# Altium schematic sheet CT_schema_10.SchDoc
size 278 x 170 mm
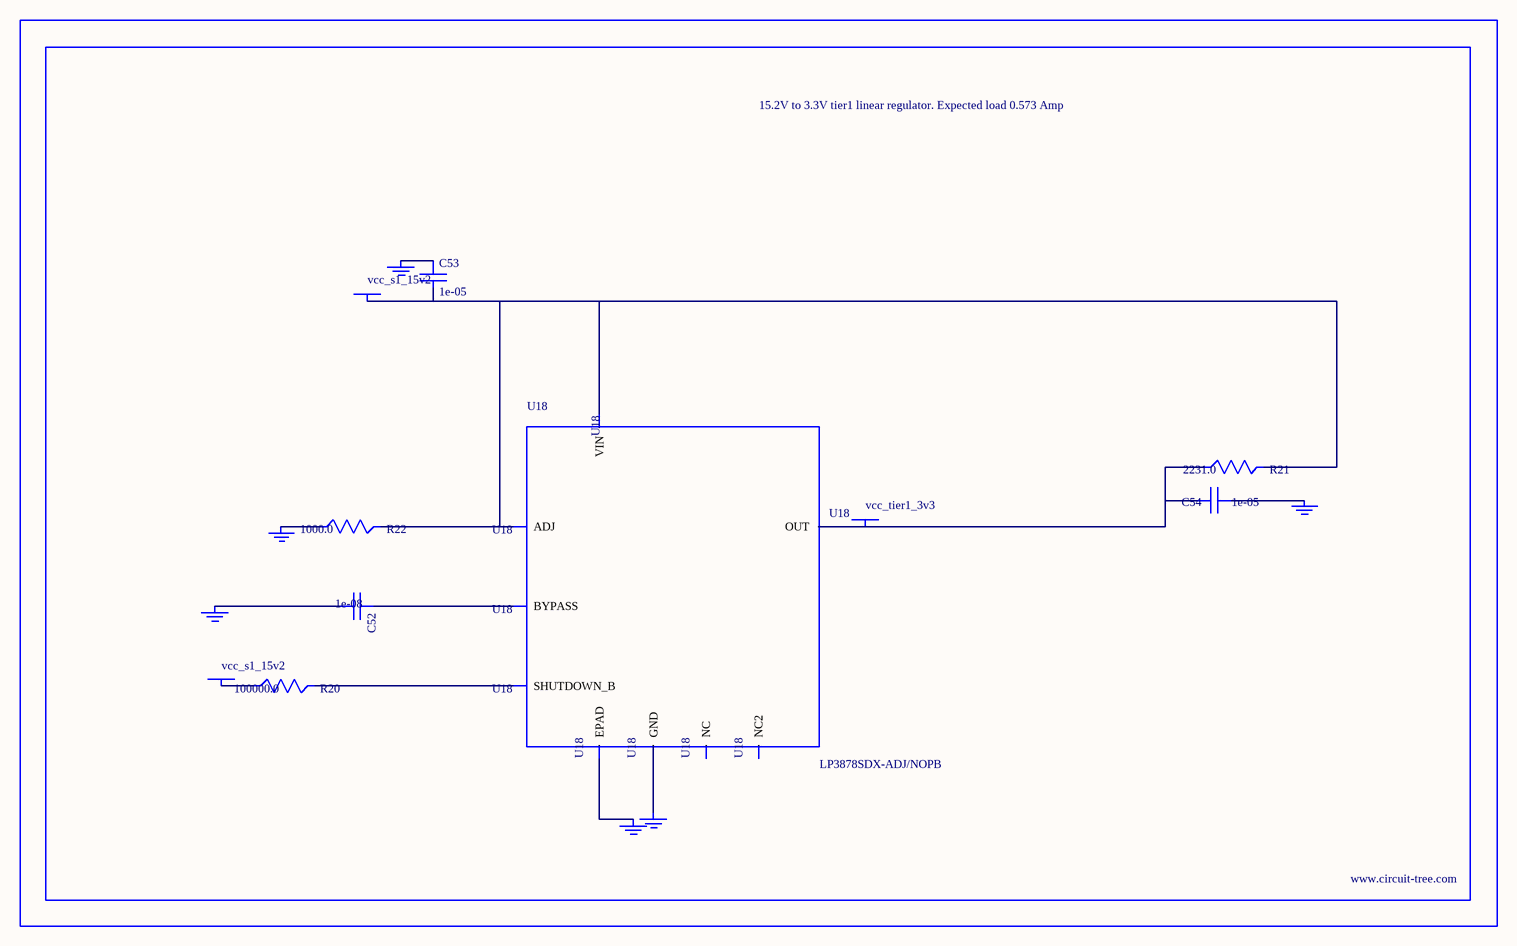
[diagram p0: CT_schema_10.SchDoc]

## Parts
BORDER9  (no value)
C52  1e-08  [C0402]
C53  1e-05  [C1210]
C54  1e-05  [C1210]
GND_INSTANCE_9_0  (no value)
GND_INSTANCE_9_1  (no value)
GND_INSTANCE_9_2  (no value)
GND_INSTANCE_9_3  (no value)
GND_INSTANCE_9_4  (no value)
GND_INSTANCE_9_5  (no value)
POWER_INSTANCE_9_0  vcc_s1_15v2
POWER_INSTANCE_9_1  vcc_s1_15v2
POWER_INSTANCE_9_2  vcc_tier1_3v3
R20  100000.0  [R0603]
R21  2231.0  [R0603]
R22  1000.0  [R0603]
U18  LP3878SDX-ADJ/NOPB  [WSON-8]

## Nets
NetC52_1: C52.1 U18.1(BYPASS)
NetC52_2: C52.2 GND_INSTANCE_9_0.0(GND)
NetC53_1: C53.1 GND_INSTANCE_9_1.0(GND)
NetC53_2: C53.2 POWER_INSTANCE_9_0.0(PWR) R21.2 R22.2 U18.4(VIN) U18.6(ADJ)
NetC54_1: C54.1 GND_INSTANCE_9_2.0(GND)
NetC54_2: C54.2 POWER_INSTANCE_9_2.0(PWR) R21.1 U18.5(OUT)
NetGND_INSTANCE_9_3_0: GND_INSTANCE_9_3.0(GND) R22.1
NetGND_INSTANCE_9_4_0: GND_INSTANCE_9_4.0(GND) U18.PAD(EPAD)
NetGND_INSTANCE_9_5_0: GND_INSTANCE_9_5.0(GND) U18.3(GND)
NetPOWER_INSTANCE_9_1_0: POWER_INSTANCE_9_1.0(PWR) R20.1
NetR20_2: R20.2 U18.8(SHUTDOWN_B)

Not connected (* = marked no-connect by the designer): U18 2(NC) 7(NC2)

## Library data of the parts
BORDER9 = BORDER_PAGE9
C52 = C0402C103K3RAC
C53 = C1210C106K5PACTU
C54 = GRM32DR61E106MA12L
GND_INSTANCE_9_0-GND_INSTANCE_9_5 = GND
POWER_INSTANCE_9_0-POWER_INSTANCE_9_2 = PWR
R20 = RC0603JR-07100KL
R21 = R21
R22 = RC0603JR-071KL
